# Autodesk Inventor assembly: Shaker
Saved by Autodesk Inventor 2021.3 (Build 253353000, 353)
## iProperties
Created: 2022-03
Part Number: Shaker
Document SubType Name: Assembly
Designer: Administrator
Title: Shaker v1
Author: Administrator
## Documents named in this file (4)
- c:\worker\convert-fusion-r02\tmp\job-1\2083\output\files\1a6e1000-68dc-434b-b675-10397019b60a\453bcbd0-6e34-4d7b-9211-b16ab2d1d84f.iam
- c:\worker\convert-fusion-r02\tmp\job-1\2083\output\files\1a6e1000-68dc-434b-b675-10397019b60a\Actual Shaker Stand v1.ipt
- c:\worker\convert-fusion-r02\tmp\job-1\2083\output\files\1a6e1000-68dc-434b-b675-10397019b60a\Shacker Pin Small v1.ipt
- c:\worker\convert-fusion-r02\tmp\job-1\2083\output\files\1a6e1000-68dc-434b-b675-10397019b60a\Part6.ipt
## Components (4 placed, 3 different names)
1. Actual Shaker Stand v1:1
2. Shacker Pin Small v1:1
3. Shacker Pin Small v1:2
4. Part6
